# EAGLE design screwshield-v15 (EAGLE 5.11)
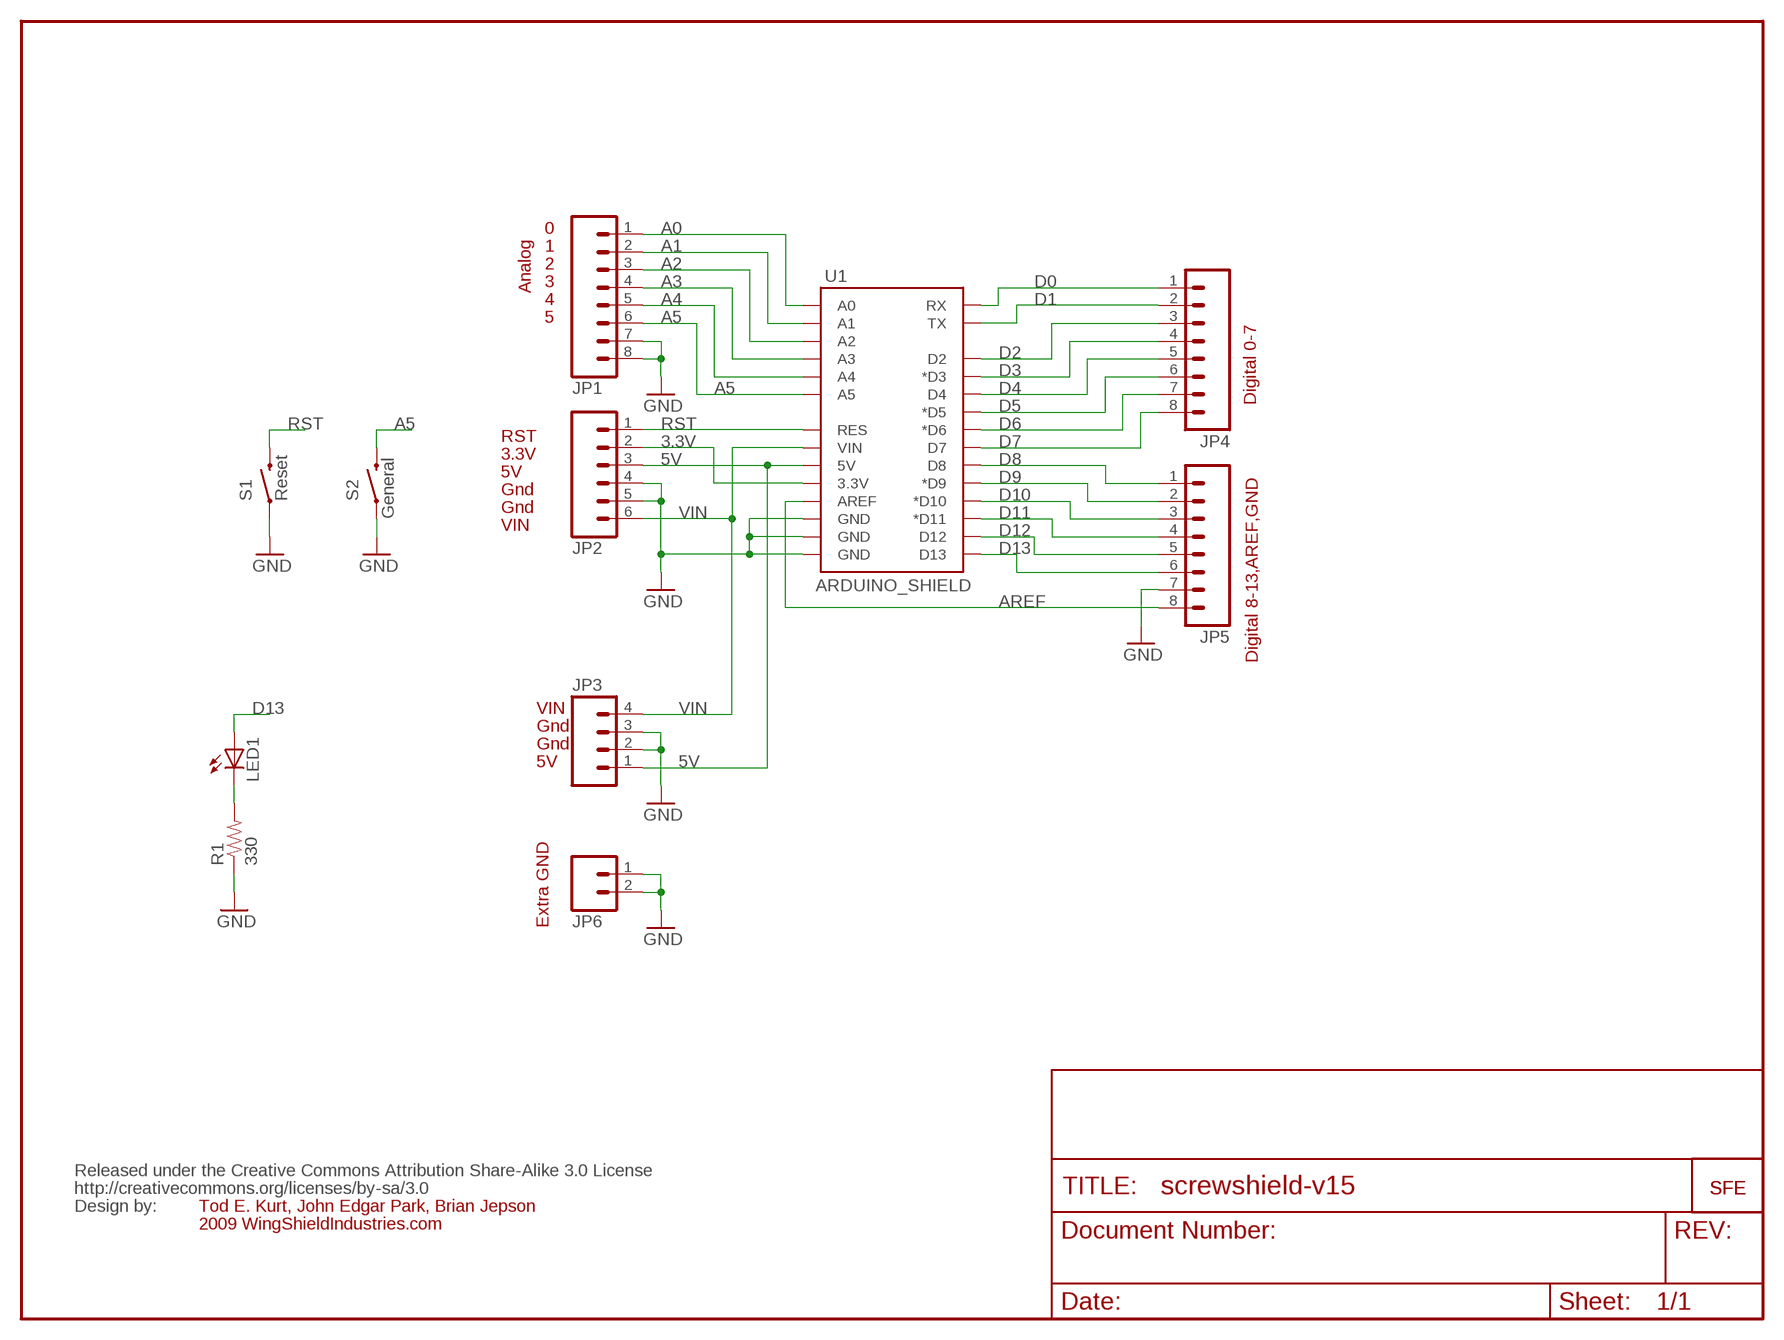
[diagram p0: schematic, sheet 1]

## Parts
JP1  M083.5MM-8  [SCREWTERMINAL-3.5MM-8]
JP2  M063.5MM-6  [SCREWTERMINAL-3.5MM-6]
JP3  M04SCREW  [SCREWTERMINAL-3.5MM-4]
JP4  M083.5MM-8  [SCREWTERMINAL-3.5MM-8]
JP5  M083.5MM-8  [SCREWTERMINAL-3.5MM-8]
JP6  M023.5MM  [SCREWTERMINAL-3.5MM-2]
JP7  LOGO-SFENEW  [SFE-NEW-WEBLOGO]
JP8  LOGO-SFESK  [SFE-LOGO-FLAME]
LED1  LED5MM  [LED5MM]
R1  330  RESISTORPTH1  [AXIAL-0.3]
S1  Reset  SWITCH-MOMENTARY-2PTH  [TACTILE-PTH]
S2  General  SWITCH-MOMENTARY-2PTH  [TACTILE-PTH]
U1  ARDUINO_SHIELD  ARDUINO_SHIELDNOHOLES  [DUEMILANOVE_SHIELD_NOHOLES]
U$1  CREATIVE_COMMONS  [CREATIVE_COMMONS]

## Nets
3.3V: JP2.2 U1.3.3V
5V: JP2.3 JP3.1 U1.5V
A0: JP1.1 U1.A0
A1: JP1.2 U1.A1
A2: JP1.3 U1.A2
A3: JP1.4 U1.A3
A4: JP1.5 U1.A4
A5: JP1.6 S2.3 U1.A5
AREF: JP5.8 U1.AREF
D0: JP4.1 U1.RX
D1: JP4.2 U1.TX
D2: JP4.3 U1.D2
D3: JP4.4 U1.D3(*D3)
D4: JP4.5 U1.D4
D5: JP4.6 U1.D5(*D5)
D6: JP4.7 U1.D6(*D6)
D7: JP4.8 U1.D7
D8: JP5.1 U1.D8
D9: JP5.2 U1.D9(*D9)
D10: JP5.3 U1.D10(*D10)
D11: JP5.4 U1.D11(*D11)
D12: JP5.5 U1.D12
D13: JP5.6 LED1.A U1.D13
GND: JP1.7 JP1.8 JP2.4 JP2.5 JP3.2 JP3.3 JP5.7 JP6.1 JP6.2 R1.P$1 S1.1 S2.1 U1.GND@0(GND) U1.GND@1(GND) U1.GND@2(GND)
N$6: LED1.K(C) R1.P$2
RST: JP2.1 S1.3 U1.RES
VIN: JP2.6 JP3.4 U1.VIN

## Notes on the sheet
- 0
- Analog
- 1
- 2
- 3
- 4
- 5
- Digital 0-7
- RST
- 3.3V
- 5V
- Gnd
- Gnd
- VIN
- Digital 8-13,AREF,GND
- VIN
- Gnd
- Gnd
- 5V
- Extra GND
- Tod E. Kurt, John Edgar Park, Brian Jepson
- 2009 WingShieldIndustries.com

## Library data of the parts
JP1 JP4 JP5 = SparkFun:M08: Header 8 Standard 8-pin 0.1" header. Use with straight break away headers (SKU : PRT-00116), right angle break away headers (PRT-00553), swiss pins (PRT-00743), machine pins (PRT-00117), and female headers (PRT-00115).
JP2 = SparkFun:M06: Header 6 Standard 6-pin 0.1" header. Use with straight break away headers (SKU : PRT-00116), right angle break away headers (PRT-00553), swiss pins (PRT-00743), machine pins (PRT-00117), and female headers (PRT-00115). Molex polarized connector foot print use with SKU : PRT-08094 with associated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
JP3 = SparkFun:M04: Header 4 Standard 4-pin 0.1" header. Use with straight break away headers (SKU : PRT-00116), right angle break away headers (PRT-00553), swiss pins (PRT-00743), machine pins (PRT-00117), and female headers (PRT-00115). Molex polarized connector foot print use with SKU : PRT-08231 with associated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
JP6 = SparkFun:M02: Header 2
JP7 JP8 = SparkFun:LOGO-SFE: Spark Fun Electronics PCB Logo
LED1 = SparkFun:LED: LEDs
R1 = SparkFun:RESISTOR: Resistor
S1 S2 = SparkFun:SWITCH-MOMENTARY-2
U1 = SparkFun:ARDUINO_SHIELD
U$1 = SparkFun:CREATIVE_COMMONS

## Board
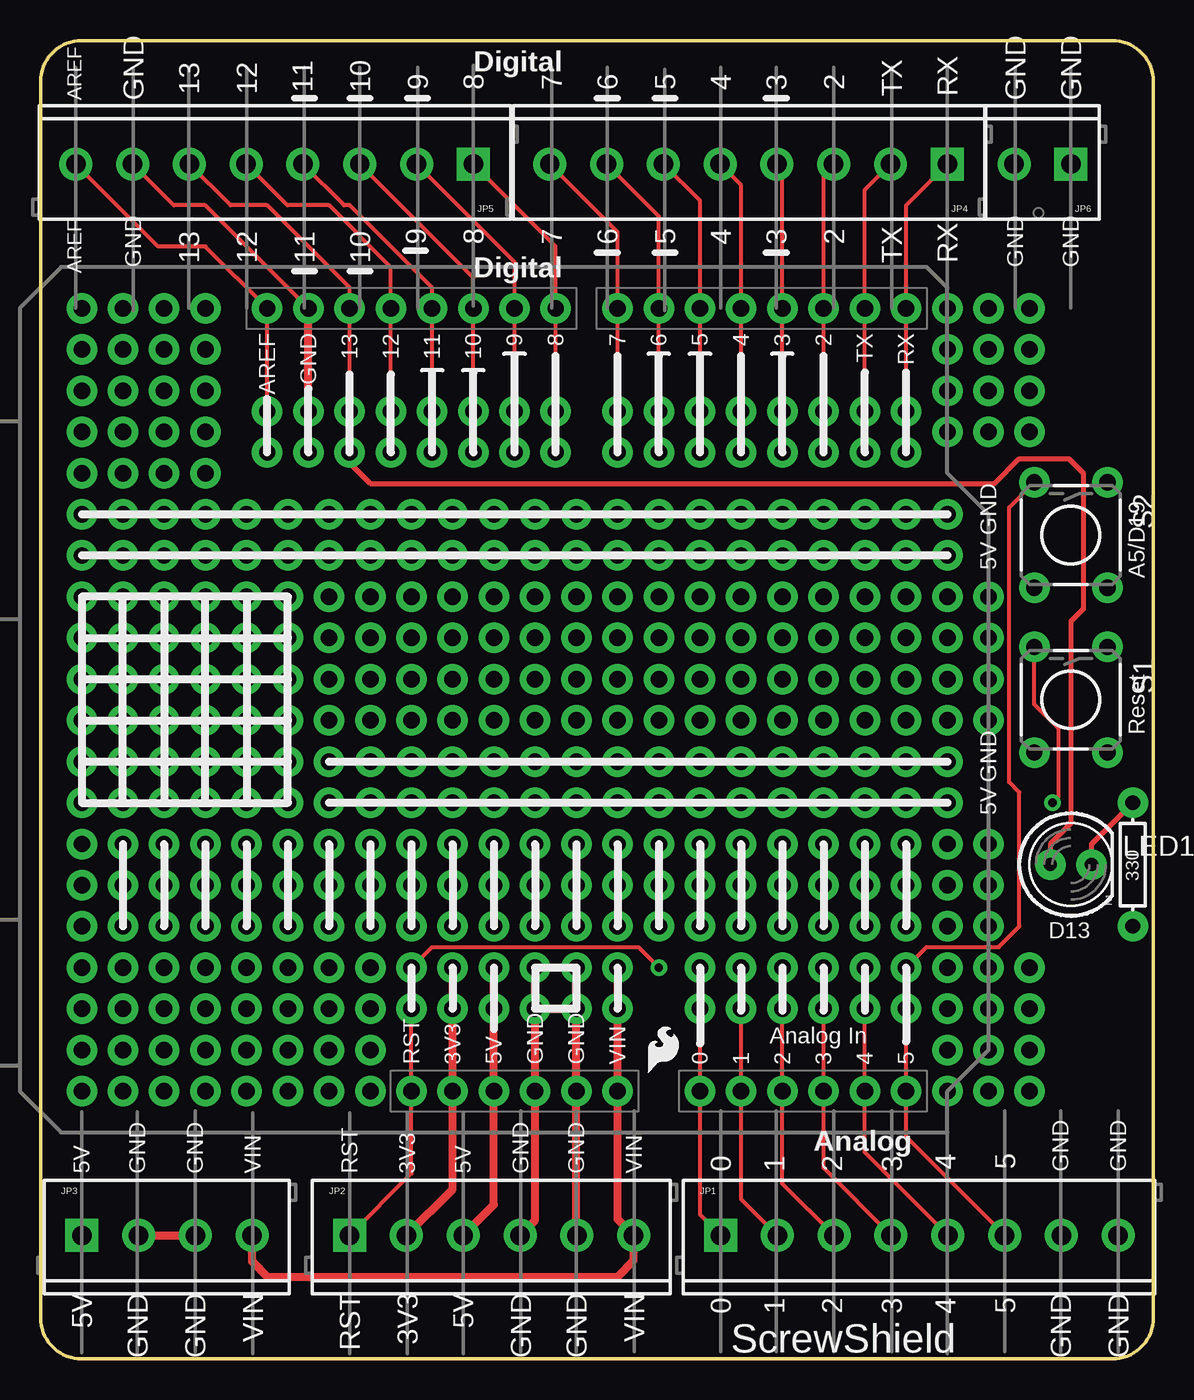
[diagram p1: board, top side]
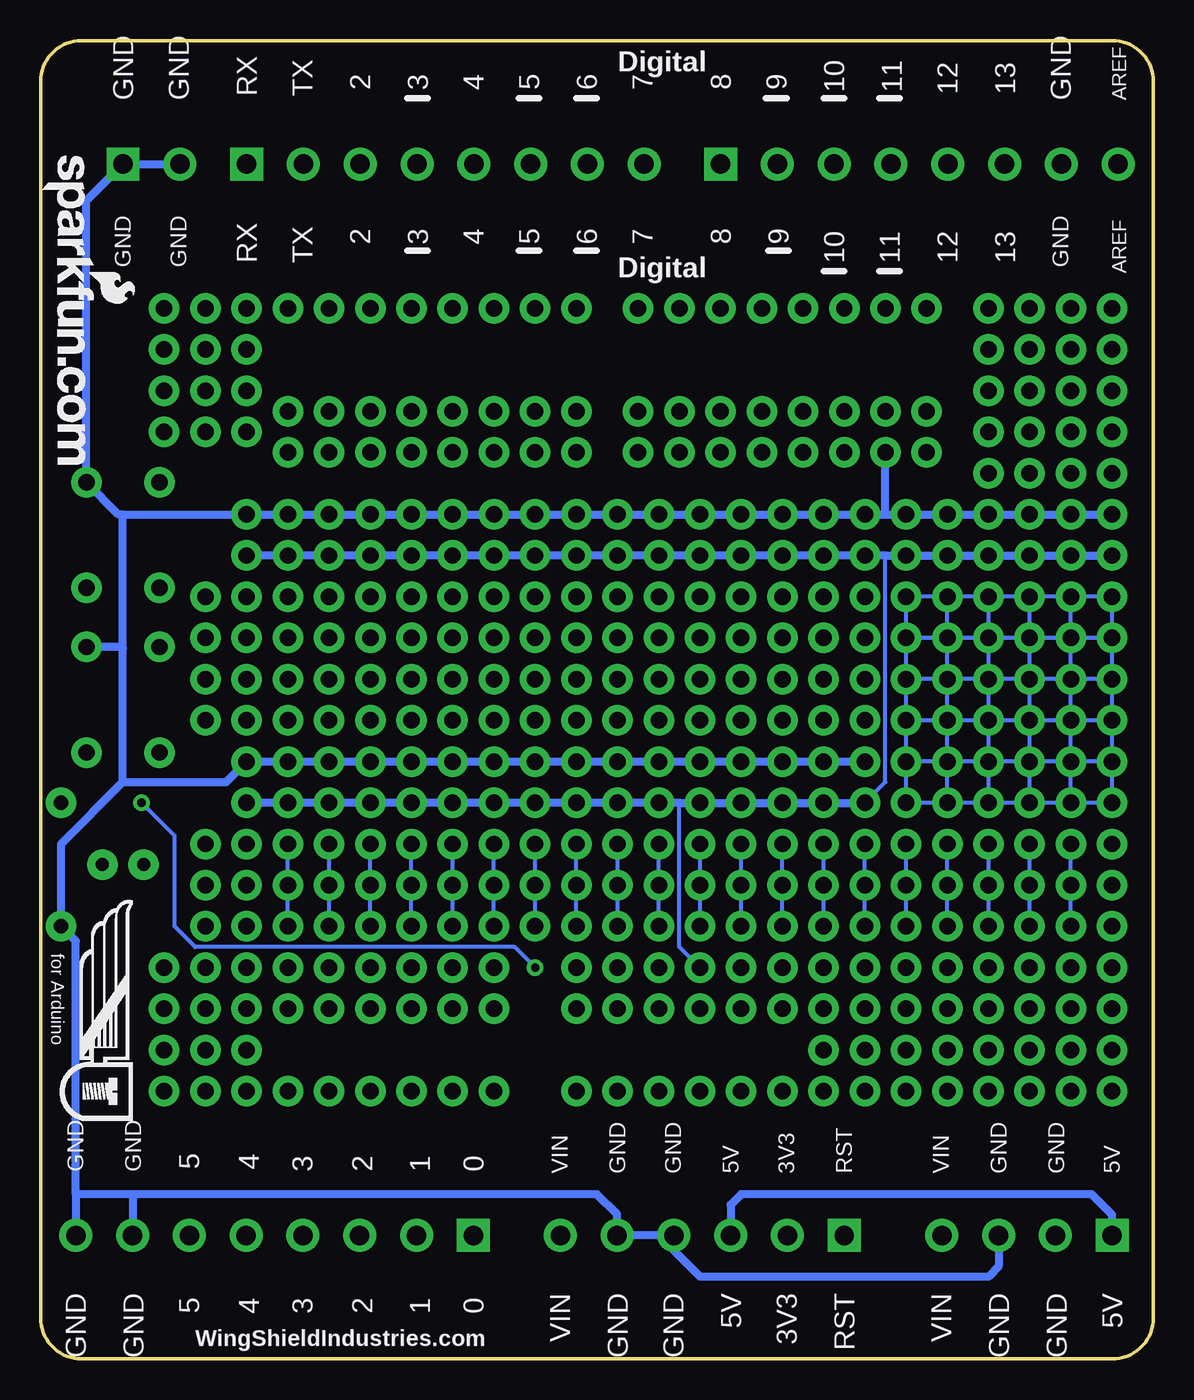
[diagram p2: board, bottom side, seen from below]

Size 68.58 x 81.28 mm. Coordinates in mm from the lower left corner, seen from the top.
Outline: 2.54,0 66.04,0 arc90 68.58,2.54 68.58,78.74 arc90 66.04,81.28 2.54,81.28 arc90 0,78.74 0,2.54 arc90 2.54,0
Copper layers (1*16): Top 0.035mm / dielectric 1.5mm / Bottom 0.035mm
Design rules "SparkFun": minimum track width 8mil, minimum drill 20mil, track to track 8mil, track to pad 8mil, pad to pad 8mil, via to via 8mil, smd to smd 8mil, copper to edge 9mil, drill to drill 8mil, minimum pad ring 12mil, minimum via ring 10mil, stop-mask expansion 4mil, vias tented up to drill 20mil, thermal gap 10mil

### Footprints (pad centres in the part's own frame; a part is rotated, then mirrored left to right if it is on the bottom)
SCREWTERMINAL-3.5MM-8 = drill 1.2 pad 2.032 square: 1 0,0 | drill 1.2 pad 2.032 round: 2 3.5,0; 3 7,0; 4 10.5,0; 5 14,0; 6 17.5,0; 7 21,0; 8 24.5,0
SCREWTERMINAL-3.5MM-6 = drill 1.2 pad 2.032 square: 1 0,0 | drill 1.2 pad 2.032 round: 2 3.5,0; 3 7,0; 4 10.5,0; 5 14,0; 6 17.5,0
SCREWTERMINAL-3.5MM-4 = drill 1.2 pad 2.032 square: 1 0,0 | drill 1.2 pad 2.032 round: 2 3.5,0; 3 7,0; 4 10.5,0
SCREWTERMINAL-3.5MM-2 = drill 1.2 pad 2.032 square: 1 0,0 | drill 1.2 pad 2.032 round: 2 3.5,0
LED5MM = drill 0.813 pad 1.88 round: A -1.27,0; K 1.27,0
AXIAL-0.3 = drill 0.9 pad 1.88 round: P$1 -3.81,0; P$2 3.81,0
TACTILE-PTH = drill 1.016 pad 1.88 round: 1 -3.251,2.261; 2 3.251,2.261; 3 -3.251,-2.261; 4 3.251,-2.261
DUEMILANOVE_SHIELD_NOHOLES = drill 1.016 pad 1.88 round: 3.3V 50.8,26.67; 5V 50.8,29.21; A0 50.8,41.91; A1 50.8,44.45; A2 50.8,46.99; A3 50.8,49.53; A4 50.8,52.07; A5 50.8,54.61; AREF 2.54,15.24; D2 2.54,49.53; D3 2.54,46.99; D4 2.54,44.45; D5 2.54,41.91; D6 2.54,39.37; D7 2.54,36.83; D8 2.54,33.02; D9 2.54,30.48; D10 2.54,27.94; D11 2.54,25.4; D12 2.54,22.86; D13 2.54,20.32; GND@0 50.8,31.75; GND@1 50.8,34.29; GND@2 2.54,17.78; RES 50.8,24.13; RX 2.54,54.61; TX 2.54,52.07; VIN 50.8,36.83

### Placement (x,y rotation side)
JP1  41.91,7.62 0 top
JP2  19.05,7.62 0 top
JP3  2.54,7.62 0 top
JP4  55.88,73.66 180 top
JP5  26.67,73.66 180 top
JP6  63.5,73.66 180 top
JP7  68.45,74.17 270 bottom
JP8  37.46,17.65 0 top
LED1  63.5,30.48 0 top
R1  67.31,30.48 90 top
S1  63.5,40.64 270 top
S2  63.5,50.8 270 top
U1  -1.27,67.31 270 top
U$1  not placed on the board

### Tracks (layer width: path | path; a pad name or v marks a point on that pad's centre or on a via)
3.3V  (via drill 1.02 pad 1.88)
  Top 0.508: JP2.2 25.4,10.47 U1.3.3V v25.4,21.59 v25.4,24.13
5V  (via drill 1.02 pad 1.88)
  Top 0.508: v27.94,24.13 v27.94,21.59 U1.5V 27.94,9.51 JP2.3
  Bottom 0.254: 16.51,49.53 16.51,35.56 v17.78,34.29 | v27.94,24.13 29.21,25.4 29.21,34.29
  Bottom 0.508: v55.88,34.29 v53.34,34.29 v50.8,34.29 v48.26,34.29 v45.72,34.29 v43.18,34.29 v40.64,34.29 v38.1,34.29 v35.56,34.29 v33.02,34.29 v30.48,34.29 29.21,34.29 v27.94,34.29 v25.4,34.29 v22.86,34.29 v20.32,34.29 v17.78,34.29 | v2.54,49.53 v5.08,49.53 v7.62,49.53 v10.16,49.53 v12.7,49.53 v15.24,49.53 16.51,49.53 v17.78,49.53 v20.32,49.53 v22.86,49.53 v25.4,49.53 v27.94,49.53 v30.48,49.53 v33.02,49.53 v35.56,49.53 v38.1,49.53 v40.64,49.53 v43.18,49.53 v45.72,49.53 v48.26,49.53 v50.8,49.53 v53.34,49.53 v55.88,49.53 | JP2.3 26.05,9.51 25.4,10.16 3.81,10.16 2.54,8.89 JP3.1
A0  (via drill 1.02 pad 1.88)
  Top 0.254: v40.64,24.13 v40.64,21.59 U1.A0 40.64,8.89 JP1.1
A1  (via drill 1.02 pad 1.88)
  Top 0.254: v43.18,24.13 v43.18,21.59 U1.A1 43.18,9.85 JP1.2
A2  (via drill 1.02 pad 1.88)
  Top 0.254: v45.72,24.13 v45.72,21.59 U1.A2 45.72,10.81 JP1.3
A3  (via drill 1.02 pad 1.88)
  Top 0.254: v48.26,24.13 v48.26,21.59 U1.A3 48.26,11.77 JP1.4
A4  (via drill 1.02 pad 1.88)
  Top 0.254: v50.8,24.13 v50.8,21.59 U1.A4 50.8,12.73 JP1.5
A5  (via drill 1.02 pad 1.88)
  Top 0.254: JP1.6 53.34,13.69 U1.A5 v53.34,21.59 v53.34,24.13 54.61,25.4 59.05,25.4 60.32,26.67 60.32,34.92 59.69,35.56 59.69,52.5 S2.3
AREF  (via drill 1.02 pad 1.88)
  Top 0.254: v13.97,55.88 v13.97,58.42 U1.AREF 10.16,68.58 7.25,68.58 JP5.8
B1  (via drill 1.02 pad 1.88)
  Bottom 0.254: v5.08,31.75 v5.08,29.21 v5.08,26.67
B2  (via drill 1.02 pad 1.88)
  Bottom 0.254: v7.62,26.67 v7.62,29.21 v7.62,31.75
B3  (via drill 1.02 pad 1.88)
  Bottom 0.254: v10.16,31.75 v10.16,29.21 v10.16,26.67
B4  (via drill 1.02 pad 1.88)
  Bottom 0.254: v12.7,26.67 v12.7,29.21 v12.7,31.75
B5  (via drill 1.02 pad 1.88)
  Bottom 0.254: v15.24,26.67 v15.24,29.21 v15.24,31.75
B6  (via drill 1.02 pad 1.88)
  Bottom 0.254: v17.78,31.75 v17.78,29.21 v17.78,26.67
B7  (via drill 1.02 pad 1.88)
  Bottom 0.254: v20.32,26.67 v20.32,29.21 v20.32,31.75
B8  (via drill 1.02 pad 1.88)
  Bottom 0.254: v22.86,31.75 v22.86,29.21 v22.86,26.67
B9  (via drill 1.02 pad 1.88)
  Bottom 0.254: v25.4,26.67 v25.4,29.21 v25.4,31.75
B10  (via drill 1.02 pad 1.88)
  Bottom 0.254: v27.94,31.75 v27.94,29.21 v27.94,26.67
B11  (via drill 1.02 pad 1.88)
  Bottom 0.254: v30.48,26.67 v30.48,29.21 v30.48,31.75
B12  (via drill 1.02 pad 1.88)
  Bottom 0.254: v33.02,31.75 v33.02,29.21 v33.02,26.67
B13  (via drill 1.02 pad 1.88)
  Bottom 0.254: v35.56,26.67 v35.56,29.21 v35.56,31.75
B14  (via drill 1.02 pad 1.88)
  Bottom 0.254: v38.1,31.75 v38.1,29.21 v38.1,26.67
B15  (via drill 1.02 pad 1.88)
  Bottom 0.254: v40.64,26.67 v40.64,29.21 v40.64,31.75
B16  (via drill 1.02 pad 1.88)
  Bottom 0.254: v43.18,31.75 v43.18,29.21 v43.18,26.67
B17  (via drill 1.02 pad 1.88)
  Bottom 0.254: v45.72,26.67 v45.72,29.21 v45.72,31.75
B18  (via drill 1.02 pad 1.88)
  Bottom 0.254: v48.26,31.75 v48.26,29.21 v48.26,26.67
B19  (via drill 1.02 pad 1.88)
  Bottom 0.254: v50.8,26.67 v50.8,29.21 v50.8,31.75
B20  (via drill 1.02 pad 1.88)
  Bottom 0.254: v53.34,31.75 v53.34,29.21 v53.34,26.67
B21  (via drill 1.02 pad 1.88)
  other vias: 55.88,29.21
CB1  (via drill 1.02 pad 1.88)
  Bottom 0.254: v12.7,46.99 v15.24,46.99 v15.24,44.45 | v15.24,41.91 v15.24,44.45 | v12.7,44.45 v15.24,44.45 | v12.7,44.45 v12.7,46.99 | v10.16,46.99 v12.7,46.99 | v7.62,46.99 v10.16,46.99 | v10.16,44.45 v12.7,44.45 | v10.16,44.45 v10.16,46.99 | v12.7,41.91 v15.24,41.91 | v12.7,41.91 v12.7,44.45 | v15.24,39.37 v15.24,41.91 | v15.24,36.83 v15.24,39.37 | v12.7,39.37 v15.24,39.37 | v12.7,39.37 v12.7,41.91 | v10.16,41.91 v12.7,41.91 | v10.16,41.91 v10.16,44.45 | v7.62,44.45 v10.16,44.45 | v7.62,44.45 v7.62,46.99 | v5.08,46.99 v7.62,46.99 | v5.08,46.99 v2.54,46.99 v2.54,44.45 | v5.08,44.45 v7.62,44.45 | v5.08,44.45 v5.08,46.99 | v7.62,41.91 v10.16,41.91 | v7.62,41.91 v7.62,44.45 | v10.16,39.37 v12.7,39.37 | v10.16,39.37 v10.16,41.91 | v12.7,36.83 v15.24,36.83 | v12.7,36.83 v12.7,39.37 | v15.24,36.83 v15.24,34.29 v12.7,34.29 | v12.7,34.29 v12.7,36.83 | v10.16,36.83 v12.7,36.83 | v10.16,36.83 v10.16,39.37 | v7.62,39.37 v10.16,39.37 | v7.62,39.37 v7.62,41.91 | v2.54,44.45 v5.08,44.45 | v5.08,41.91 v7.62,41.91 | v5.08,41.91 v5.08,44.45 | v2.54,41.91 v5.08,41.91 | v2.54,41.91 v2.54,44.45 | v5.08,39.37 v7.62,39.37 | v5.08,39.37 v5.08,41.91 | v7.62,36.83 v10.16,36.83 | v7.62,36.83 v7.62,39.37 | v10.16,34.29 v12.7,34.29 | v10.16,34.29 v10.16,36.83 | v7.62,34.29 v10.16,34.29 | v7.62,34.29 v7.62,36.83 | v2.54,39.37 v5.08,39.37 | v2.54,39.37 v2.54,41.91 | v5.08,36.83 v7.62,36.83 | v5.08,36.83 v5.08,39.37 | v2.54,36.83 v5.08,36.83 | v2.54,36.83 v2.54,39.37 | v5.08,34.29 v7.62,34.29 | v5.08,34.29 v5.08,36.83 | v5.08,34.29 v2.54,34.29 v2.54,36.83
D0  (via drill 1.02 pad 1.88)
  Top 0.254: JP4.1 53.34,71.12 U1.RX v53.34,58.42 v53.34,55.88
D1  (via drill 1.02 pad 1.88)
  Top 0.254: JP4.2 50.8,72.08 U1.TX v50.8,58.42 v50.8,55.88
D2  (via drill 1.02 pad 1.88)
  Top 0.254: JP4.3 48.26,73.04 U1.D2 v48.26,58.42 v48.26,55.88
D3  (via drill 1.02 pad 1.88)
  Top 0.254: JP4.4 45.72,73.32 U1.D3 v45.72,58.42 v45.72,55.88
D4  (via drill 1.02 pad 1.88)
  Top 0.254: JP4.5 43.18,72.36 U1.D4 v43.18,58.42 v43.18,55.88
D5  (via drill 1.02 pad 1.88)
  Top 0.254: JP4.6 40.64,71.4 U1.D5 v40.64,58.42 v40.64,55.88
D6  (via drill 1.02 pad 1.88)
  Top 0.254: JP4.7 38.1,70.44 U1.D6 v38.1,58.42 v38.1,55.88
D7  (via drill 1.02 pad 1.88)
  Top 0.254: JP4.8 35.56,69.48 U1.D7 v35.56,58.42 v35.56,55.88
D8  (via drill 1.02 pad 1.88)
  Top 0.254: JP5.1 31.75,68.58 U1.D8 v31.75,58.42 v31.75,55.88
D9  (via drill 1.02 pad 1.88)
  Top 0.254: JP5.2 29.21,67.62 U1.D9 v29.21,55.88 v29.21,58.42
D10  (via drill 1.02 pad 1.88)
  Top 0.254: JP5.3 26.67,66.66 U1.D10 v26.67,58.42 v26.67,55.88
D11  (via drill 1.02 pad 1.88)
  Top 0.254: JP5.4 18.71,71.12 19.05,71.12 24.13,66.04 U1.D11 v24.13,55.88 v24.13,58.42
D12  (via drill 1.02 pad 1.88)
  Top 0.254: JP5.5 15.21,71.12 17.78,71.12 21.59,67.31 U1.D12 v21.59,58.42 v21.59,55.88
D13  (via drill 1.02 pad 1.88)
  Top 0.254: JP5.6 11.71,71.12 13.97,71.12 19.05,66.04 U1.D13 v19.05,58.42 v19.05,55.88
  Top 0.305: v19.05,55.88 19.05,55.24 20.32,53.98 58.8,53.98 60.32,55.5 63.37,55.5 64.26,54.61 64.26,46.23 63.5,45.47 63.5,33.02 62.23,31.75 LED1.A
GND  (via drill 1.02 pad 1.88)
  Top 0.254: U1.GND@2 10.16,71.12 8.21,71.12 JP5.7
  Top 0.508: JP3.2 JP3.3 | v33.02,21.59 U1.GND@1 33.02,7.65 JP2.5 | JP2.4 30.48,8.55 U1.GND@0 v30.48,21.59 | v30.48,21.59 v30.48,24.13 v33.02,24.13 v33.02,21.59 | v30.48,21.59 v33.02,21.59 | U1.GND@2 v16.51,58.42 v16.51,55.88
  Bottom 0.254: JP2.5 33.02,7.59
  Bottom 0.508: 16.51,52.07 v17.78,52.07 v20.32,52.07 v22.86,52.07 v25.4,52.07 v27.94,52.07 v30.48,52.07 v33.02,52.07 v35.56,52.07 v38.1,52.07 v40.64,52.07 v43.18,52.07 v45.72,52.07 v48.26,52.07 v50.8,52.07 v53.34,52.07 v55.88,52.07 63.5,52.07 | 16.51,52.07 v15.24,52.07 v12.7,52.07 v10.16,52.07 v7.62,52.07 v5.08,52.07 v2.54,52.07 | JP3.3 9.54,5.7 10.16,5.08 27.94,5.08 29.55,6.69 JP2.4 JP2.5 33.05,8.92 34.29,10.16 62.87,10.16 | 63.5,52.07 63.78,52.07 S2.1 65.76,71.4 JP6.1 JP6.2 | 66.41,10.16 JP1.8 | 66.41,10.16 66.41,25.77 R1.P$1 67.31,31.75 63.5,35.56 | 62.87,10.16 66.41,10.16 | JP1.7 62.91,10.12 62.87,10.16 | 63.5,35.56 63.5,43.81 | 63.5,43.81 63.5,52.07 | S1.1 63.58,43.89 63.5,43.81 | v17.78,36.83 v20.32,36.83 v22.86,36.83 v25.4,36.83 v27.94,36.83 v30.48,36.83 v33.02,36.83 v35.56,36.83 v38.1,36.83 v40.64,36.83 v43.18,36.83 v45.72,36.83 v48.26,36.83 v50.8,36.83 v53.34,36.83 v55.88,36.83 57.15,35.56 63.5,35.56 | 16.51,52.07 v16.51,55.88
N$2  (via drill 1.02 pad 1.88)
  other vias: 55.88,31.75
N$3  (via drill 1.02 pad 1.88)
  other vias: 55.88,26.67
N$4  (via drill 1.02 pad 1.88)
  other vias: 2.54,16.51
N$5  (via drill 1.02 pad 1.88)
  other vias: 2.54,19.05
N$6
  Top 0.305: LED1.K 64.77,31.75 R1.P$2
N$9  (via drill 1.02 pad 1.88)
  other vias: 2.54,24.13
N$10  (via drill 1.02 pad 1.88)
  other vias: 2.54,21.59
N$11  (via drill 1.02 pad 1.88)
  other vias: 5.08,24.13
N$12  (via drill 1.02 pad 1.88)
  other vias: 5.08,59.69
N$13  (via drill 1.02 pad 1.88)
  other vias: 5.08,57.15
N$14  (via drill 1.02 pad 1.88)
  other vias: 7.62,57.15
N$15  (via drill 1.02 pad 1.88)
  other vias: 7.62,59.69
N$16  (via drill 1.02 pad 1.88)
  other vias: 10.16,59.69
N$17  (via drill 1.02 pad 1.88)
  other vias: 10.16,57.15
N$18  (via drill 1.02 pad 1.88)
  other vias: 7.62,24.13
N$19  (via drill 1.02 pad 1.88)
  other vias: 10.16,24.13
N$20  (via drill 1.02 pad 1.88)
  other vias: 12.7,24.13
N$22  (via drill 1.02 pad 1.88)
  other vias: 15.24,24.13
N$24  (via drill 1.02 pad 1.88)
  other vias: 17.78,24.13
N$25  (via drill 1.02 pad 1.88)
  other vias: 20.32,24.13
N$26  (via drill 1.02 pad 1.88)
  other vias: 5.08,21.59
N$27  (via drill 1.02 pad 1.88)
  other vias: 7.62,21.59
N$28  (via drill 1.02 pad 1.88)
  other vias: 10.16,21.59
N$29  (via drill 1.02 pad 1.88)
  other vias: 12.7,21.59
N$30  (via drill 1.02 pad 1.88)
  other vias: 15.24,21.59
N$31  (via drill 1.02 pad 1.88)
  other vias: 17.78,21.59
N$32  (via drill 1.02 pad 1.88)
  other vias: 20.32,21.59
N$33  (via drill 1.02 pad 1.88)
  other vias: 55.88,24.13
N$34  (via drill 1.02 pad 1.88)
  other vias: 58.42,24.13
N$35  (via drill 1.02 pad 1.88)
  other vias: 60.96,24.13
N$38  (via drill 1.02 pad 1.88)
  other vias: 55.88,21.59
N$39  (via drill 1.02 pad 1.88)
  other vias: 58.42,21.59
N$40  (via drill 1.02 pad 1.88)
  other vias: 60.96,21.59
N$43  (via drill 1.02 pad 1.88)
  other vias: 55.88,59.69
N$44  (via drill 1.02 pad 1.88)
  other vias: 58.42,59.69
N$45  (via drill 1.02 pad 1.88)
  other vias: 60.96,59.69
N$49  (via drill 1.02 pad 1.88)
  other vias: 55.88,57.15
N$51  (via drill 1.02 pad 1.88)
  other vias: 58.42,57.15
N$52  (via drill 1.02 pad 1.88)
  other vias: 60.96,57.15
N$53  (via drill 1.02 pad 1.88)
  other vias: 2.54,26.67
N$75  (via drill 1.02 pad 1.88)
  other vias: 58.42,26.67
N$80  (via drill 1.02 pad 1.88)
  other vias: 2.54,29.21
N$102  (via drill 1.02 pad 1.88)
  other vias: 58.42,29.21
N$107  (via drill 1.02 pad 1.88)
  other vias: 2.54,31.75
N$129  (via drill 1.02 pad 1.88)
  other vias: 58.42,31.75
N$194  (via drill 1.02 pad 1.88)
  other vias: 17.78,39.37
N$195  (via drill 1.02 pad 1.88)
  other vias: 20.32,39.37
N$196  (via drill 1.02 pad 1.88)
  other vias: 22.86,39.37
N$197  (via drill 1.02 pad 1.88)
  other vias: 25.4,39.37
N$198  (via drill 1.02 pad 1.88)
  other vias: 27.94,39.37
N$199  (via drill 1.02 pad 1.88)
  other vias: 30.48,39.37
N$200  (via drill 1.02 pad 1.88)
  other vias: 33.02,39.37
N$201  (via drill 1.02 pad 1.88)
  other vias: 35.56,39.37
N$202  (via drill 1.02 pad 1.88)
  other vias: 38.1,39.37
N$203  (via drill 1.02 pad 1.88)
  other vias: 40.64,39.37
N$204  (via drill 1.02 pad 1.88)
  other vias: 43.18,39.37
N$205  (via drill 1.02 pad 1.88)
  other vias: 45.72,39.37
N$206  (via drill 1.02 pad 1.88)
  other vias: 48.26,39.37
N$207  (via drill 1.02 pad 1.88)
  other vias: 50.8,39.37
N$208  (via drill 1.02 pad 1.88)
  other vias: 53.34,39.37
N$209  (via drill 1.02 pad 1.88)
  other vias: 55.88,39.37
N$210  (via drill 1.02 pad 1.88)
  other vias: 58.42,39.37
N$221  (via drill 1.02 pad 1.88)
  other vias: 17.78,41.91
N$222  (via drill 1.02 pad 1.88)
  other vias: 20.32,41.91
N$223  (via drill 1.02 pad 1.88)
  other vias: 22.86,41.91
N$224  (via drill 1.02 pad 1.88)
  other vias: 25.4,41.91
N$225  (via drill 1.02 pad 1.88)
  other vias: 27.94,41.91
N$226  (via drill 1.02 pad 1.88)
  other vias: 30.48,41.91
N$227  (via drill 1.02 pad 1.88)
  other vias: 33.02,41.91
N$228  (via drill 1.02 pad 1.88)
  other vias: 35.56,41.91
N$229  (via drill 1.02 pad 1.88)
  other vias: 38.1,41.91
N$230  (via drill 1.02 pad 1.88)
  other vias: 40.64,41.91
N$231  (via drill 1.02 pad 1.88)
  other vias: 43.18,41.91
N$232  (via drill 1.02 pad 1.88)
  other vias: 45.72,41.91
N$233  (via drill 1.02 pad 1.88)
  other vias: 48.26,41.91
N$234  (via drill 1.02 pad 1.88)
  other vias: 50.8,41.91
N$235  (via drill 1.02 pad 1.88)
  other vias: 53.34,41.91
N$236  (via drill 1.02 pad 1.88)
  other vias: 55.88,41.91
N$237  (via drill 1.02 pad 1.88)
  other vias: 58.42,41.91
N$248  (via drill 1.02 pad 1.88)
  other vias: 17.78,44.45
N$249  (via drill 1.02 pad 1.88)
  other vias: 20.32,44.45
N$250  (via drill 1.02 pad 1.88)
  other vias: 22.86,44.45
N$251  (via drill 1.02 pad 1.88)
  other vias: 25.4,44.45
N$252  (via drill 1.02 pad 1.88)
  other vias: 27.94,44.45
N$253  (via drill 1.02 pad 1.88)
  other vias: 30.48,44.45
N$254  (via drill 1.02 pad 1.88)
  other vias: 33.02,44.45
N$255  (via drill 1.02 pad 1.88)
  other vias: 35.56,44.45
N$256  (via drill 1.02 pad 1.88)
  other vias: 38.1,44.45
N$257  (via drill 1.02 pad 1.88)
  other vias: 40.64,44.45
N$258  (via drill 1.02 pad 1.88)
  other vias: 43.18,44.45
N$259  (via drill 1.02 pad 1.88)
  other vias: 45.72,44.45
N$260  (via drill 1.02 pad 1.88)
  other vias: 48.26,44.45
N$261  (via drill 1.02 pad 1.88)
  other vias: 50.8,44.45
N$262  (via drill 1.02 pad 1.88)
  other vias: 53.34,44.45
N$263  (via drill 1.02 pad 1.88)
  other vias: 55.88,44.45
N$264  (via drill 1.02 pad 1.88)
  other vias: 58.42,44.45
N$275  (via drill 1.02 pad 1.88)
  other vias: 17.78,46.99
N$276  (via drill 1.02 pad 1.88)
  other vias: 20.32,46.99
N$277  (via drill 1.02 pad 1.88)
  other vias: 22.86,46.99
N$278  (via drill 1.02 pad 1.88)
  other vias: 25.4,46.99
N$279  (via drill 1.02 pad 1.88)
  other vias: 27.94,46.99
N$280  (via drill 1.02 pad 1.88)
  other vias: 30.48,46.99
N$281  (via drill 1.02 pad 1.88)
  other vias: 33.02,46.99
N$282  (via drill 1.02 pad 1.88)
  other vias: 35.56,46.99
N$283  (via drill 1.02 pad 1.88)
  other vias: 38.1,46.99
N$284  (via drill 1.02 pad 1.88)
  other vias: 40.64,46.99
N$285  (via drill 1.02 pad 1.88)
  other vias: 43.18,46.99
N$286  (via drill 1.02 pad 1.88)
  other vias: 45.72,46.99
N$287  (via drill 1.02 pad 1.88)
  other vias: 48.26,46.99
N$288  (via drill 1.02 pad 1.88)
  other vias: 50.8,46.99
N$289  (via drill 1.02 pad 1.88)
  other vias: 53.34,46.99
N$290  (via drill 1.02 pad 1.88)
  other vias: 55.88,46.99
N$291  (via drill 1.02 pad 1.88)
  other vias: 58.42,46.99
N$350  (via drill 1.02 pad 1.88)
  other vias: 2.54,54.61
N$351  (via drill 1.02 pad 1.88)
  other vias: 5.08,54.61
N$352  (via drill 1.02 pad 1.88)
  other vias: 7.62,54.61
N$353  (via drill 1.02 pad 1.88)
  other vias: 10.16,54.61
N$377  (via drill 1.02 pad 1.88)
  other vias: 2.54,57.15
N$404  (via drill 1.02 pad 1.88)
  other vias: 2.54,59.69
N$430  (via drill 1.02 pad 1.88)
  other vias: 5.08,19.05
N$431  (via drill 1.02 pad 1.88)
  other vias: 7.62,19.05
N$432  (via drill 1.02 pad 1.88)
  other vias: 10.16,19.05
N$433  (via drill 1.02 pad 1.88)
  other vias: 12.7,19.05
N$434  (via drill 1.02 pad 1.88)
  other vias: 15.24,19.05
N$435  (via drill 1.02 pad 1.88)
  other vias: 17.78,19.05
N$436  (via drill 1.02 pad 1.88)
  other vias: 20.32,19.05
N$439  (via drill 1.02 pad 1.88)
  other vias: 5.08,16.51
N$440  (via drill 1.02 pad 1.88)
  other vias: 7.62,16.51
N$441  (via drill 1.02 pad 1.88)
  other vias: 10.16,16.51
N$442  (via drill 1.02 pad 1.88)
  other vias: 12.7,16.51
N$443  (via drill 1.02 pad 1.88)
  other vias: 15.24,16.51
N$444  (via drill 1.02 pad 1.88)
  other vias: 17.78,16.51
N$445  (via drill 1.02 pad 1.88)
  other vias: 20.32,16.51
N$447  (via drill 1.02 pad 1.88)
  other vias: 2.54,62.23
N$448  (via drill 1.02 pad 1.88)
  other vias: 5.08,62.23
N$449  (via drill 1.02 pad 1.88)
  other vias: 7.62,62.23
N$450  (via drill 1.02 pad 1.88)
  other vias: 55.88,19.05
N$451  (via drill 1.02 pad 1.88)
  other vias: 58.42,19.05
N$452  (via drill 1.02 pad 1.88)
  other vias: 60.96,19.05
N$455  (via drill 1.02 pad 1.88)
  other vias: 10.16,62.23
N$457  (via drill 1.02 pad 1.88)
  other vias: 2.54,64.77
N$458  (via drill 1.02 pad 1.88)
  other vias: 5.08,64.77
N$459  (via drill 1.02 pad 1.88)
  other vias: 7.62,64.77
N$460  (via drill 1.02 pad 1.88)
  other vias: 10.16,64.77
N$464  (via drill 1.02 pad 1.88)
  other vias: 55.88,16.51
N$465  (via drill 1.02 pad 1.88)
  other vias: 58.42,16.51
N$466  (via drill 1.02 pad 1.88)
  other vias: 60.96,16.51
N$478  (via drill 1.02 pad 1.88)
  other vias: 55.88,62.23
N$479  (via drill 1.02 pad 1.88)
  other vias: 58.42,62.23
N$480  (via drill 1.02 pad 1.88)
  other vias: 60.96,62.23
N$488  (via drill 1.02 pad 1.88)
  other vias: 55.88,64.77
N$489  (via drill 1.02 pad 1.88)
  other vias: 58.42,64.77
N$490  (via drill 1.02 pad 1.88)
  other vias: 60.96,64.77
RST  (via drill 0.51, 1.02 pad 1.88)
  Top 0.254: JP2.1 22.86,11.43 U1.RES v22.86,21.59 v22.86,24.13 24.13,25.4 36.83,25.4 v38.1,24.13 | S1.3 61.24,40.36 62.74,38.86 62.74,34.67 v62.36,34.29
  Bottom 0.254: v38.1,24.13 39.37,25.4 59.05,25.4 60.32,26.67 60.32,32.26 v62.36,34.29
VIN  (via drill 1.02 pad 1.88)
  Top 0.508: JP3.4 13.04,6.01 13.97,5.08 35.56,5.08 36.55,6.07 JP2.6 35.56,8.61 U1.VIN v35.56,21.59 v35.56,24.13

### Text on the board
tPlace: Digital | AREF | GND | 13 | 12 | 11 | 10 | 9 | 8 | 7 | 6 | 5 | 4 | 3 | 2 | TX | RX | GND | GND | 9 | 8 | 7 | 6 | 5 | 4 | 3 | 2 | 13 | 12 | 11 | 10 | TX | RX | AREF | GND | Digital | GND | GND | GND | 5V | A5/D19 | Reset | GND | 5V | D13 | Analog | 0 | 1 | 2 | 3 | 4 | 5 | GND | GND | 5V | GND | GND | VIN | RST | 3V3 | 5V | GND | GND | VIN | 5V | GND | GND | VIN | RST | 3V3 | 5V | GND | GND | VIN | GND | GND | 0 | 1 | 2 | 3 | 4 | 5 | ScrewShield
bPlace: Digital | AREF | GND | 13 | 12 | 11 | 10 | 9 | 8 | 7 | 6 | 5 | 4 | 3 | 2 | TX | RX | GND | GND | 9 | 8 | 7 | 6 | 5 | 4 | 3 | 2 | 13 | 12 | 11 | 10 | TX | RX | AREF | GND | Digital | GND | GND | for Arduino | 0 | 1 | 2 | 3 | 4 | 5 | GND | GND | 5V | GND | GND | VIN | RST | 3V3 | 5V | GND | GND | VIN | 5V | GND | GND | VIN | RST | 3V3 | 5V | GND | GND | VIN | GND | GND | 0 | 1 | 2 | 3 | 4 | 5 | WingShieldIndustries.com
tNames: Tod E. Kurt, John Edgar Park, Brian Jepson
